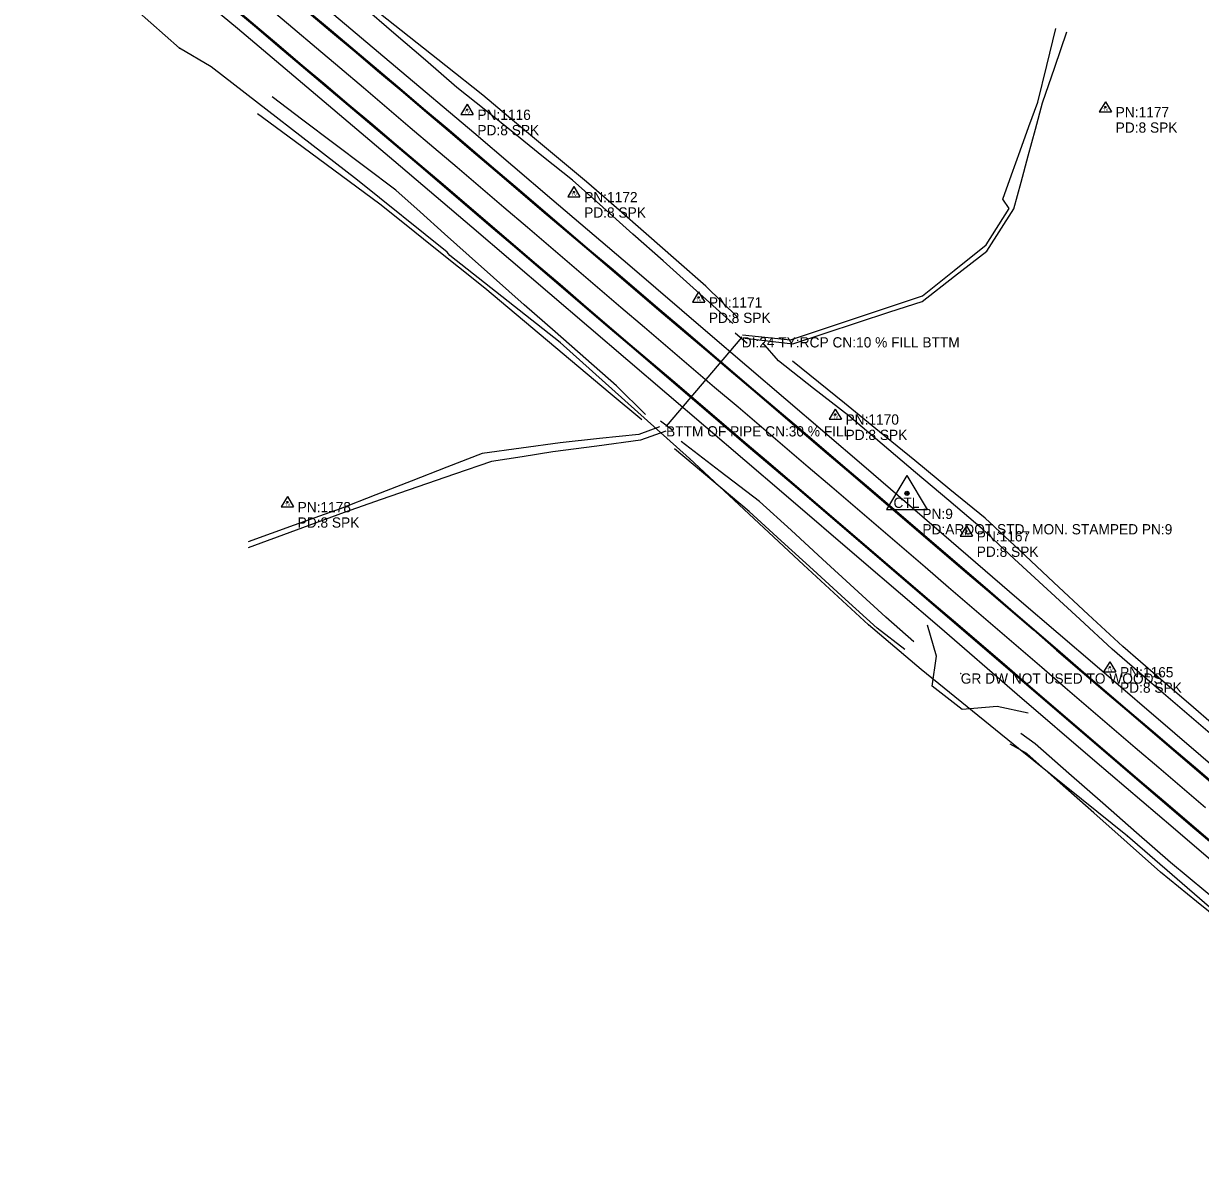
# Model space of a CAD drawing. Extents: x 878399 to 889864, y 1564003 to 1567413.
# Drawn here: x 883520 to 884094, y 1565882 to 1566437 of the extents above; entities that cross this region are included whole.
import ezdxf

# ---------------------------------------------------------------- set-up
doc = ezdxf.new("R2010")
doc.units = 0
for name, color, linetype in [('S_CROSS_DRAIN', 7, 'Continuous'), ('S_CROSS_DRAIN_ANNOT', 7, 'Continuous'), ('S_DITCHLINE', 7, 'Continuous'), ('S_DRG_PT_SYM', 7, 'Continuous'), ('S_DRIVEWAY', 7, 'Continuous'), ('S_EDGE_PAVEMENT', 7, 'Continuous'), ('S_FIBER_OPTIC_CABLE', 7, 'Continuous'), ('S_HEADWALL', 7, 'Continuous'), ('S_MSC_PT_SYM', 7, 'Continuous'), ('S_PAVEMENT_CROWN', 7, 'Continuous'), ('S_PRIMARY_CTL', 7, 'Continuous'), ('S_PRIMARY_CTL_ANNOT', 7, 'Continuous'), ('S_SECONDARY_CTL', 7, 'Continuous'), ('S_SECONDARY_CTL_ANNOT', 7, 'Continuous'), ('S_SHOULDER', 7, 'Continuous'), ('S_SURVEY_TEXT_ANNOT', 7, 'Continuous'), ('S_UTL_PT_SYM', 7, 'Continuous')]:
    doc.layers.add(name, color=color, linetype=linetype)

msp = doc.modelspace()

# ---------------------------------------------------------------- linework, layer by layer
at = {"layer": 'S_CROSS_DRAIN'}
msp.add_line((883870.47, 1566284.25), (883833.58, 1566240.87), dxfattribs=at)
at = {"layer": 'S_DITCHLINE'}
for points in [[(883868.52, 1566293.82), (883852.98, 1566309.2), (883838.44, 1566321.88), (883823.9, 1566334.56), (883809.35, 1566347.24), (883794.81, 1566359.92), (883782.15, 1566370.5), (883769.5, 1566381.09), (883756.84, 1566391.67), (883744.19, 1566402.26), (883726.29, 1566416.45), (883708.4, 1566430.65), (883690.51, 1566444.84), (883672.62, 1566459.03), (883657.19, 1566473.28), (883641.76, 1566487.53), (883626.33, 1566501.78), (883610.9, 1566516.03), (883593.87, 1566529.85), (883576.85, 1566543.67), (883559.83, 1566557.49), (883542.8, 1566571.31), (883526.07, 1566585.55), (883509.35, 1566599.78)], [(883866.04, 1566290.98), (883856.42, 1566299.66), (883846.8, 1566308.34), (883832.09, 1566321.45), (883817.39, 1566334.55), (883802.68, 1566347.66), (883787.98, 1566360.76), (883773.88, 1566372.08), (883759.79, 1566383.39), (883745.69, 1566394.71), (883731.6, 1566406.02), (883716.23, 1566419.25), (883700.87, 1566432.48), (883685.5, 1566445.7)], [(883870.77, 1566285.48), (883894.31, 1566283.02), (883910.36, 1566288.36), (883926.41, 1566293.7), (883942.46, 1566299.04), (883958.51, 1566304.38), (883974.06, 1566316.8), (883989.62, 1566329.22), (884000.82, 1566347.04), (883997.73, 1566351.58), (884001.98, 1566363.38), (884006.24, 1566375.17), (884010.49, 1566386.96), (884014.74, 1566398.75), (884019.13, 1566416.73), (884023.52, 1566434.71)], [(883872.01, 1566283.84), (883895.41, 1566281.01), (883911.16, 1566286.18), (883926.9, 1566291.36), (883942.64, 1566296.54), (883958.39, 1566301.72), (883974.19, 1566314), (883989.99, 1566326.27), (884003.13, 1566346.82), (884006.63, 1566359.75), (884010.13, 1566372.67), (884013.63, 1566385.59), (884017.13, 1566398.51), (884023.06, 1566415.81), (884028.99, 1566433.1)], [(883823.62, 1566246.5), (883809.48, 1566260.51), (883794.47, 1566273.71), (883779.45, 1566286.9), (883764.43, 1566300.1), (883749.42, 1566313.29), (883737.52, 1566323.96), (883725.63, 1566334.63), (883713.73, 1566345.3), (883701.84, 1566355.97), (883686.75, 1566367.33), (883671.65, 1566378.68), (883656.56, 1566390.03), (883641.47, 1566401.38)], [(883821.7, 1566243.92), (883806.37, 1566256.86), (883791.09, 1566269.69), (883775.8, 1566282.53), (883760.51, 1566295.36), (883745.22, 1566308.19), (883732.42, 1566318.41), (883719.62, 1566328.63), (883706.82, 1566338.85), (883694.02, 1566349.07), (883679.1, 1566360.1), (883664.18, 1566371.14), (883649.26, 1566382.17), (883634.35, 1566393.21)], [(884105.66, 1566085.17), (884087.47, 1566100.83), (884069.28, 1566116.48), (884051.09, 1566132.14), (884035.22, 1566146.81), (884019.35, 1566161.47), (884003.47, 1566176.14), (883987.6, 1566190.81), (883971.37, 1566204.59), (883955.13, 1566218.36), (883938.9, 1566232.14), (883922.66, 1566245.92), (883905.51, 1566259.29), (883888.35, 1566272.66), (883880.79, 1566281.54)], [(884107.91, 1566088.85), (884090.66, 1566103.72), (884073.42, 1566118.59), (884056.17, 1566133.46), (884039.4, 1566149.1), (884022.62, 1566164.74), (884005.85, 1566180.39), (883989.08, 1566196.03), (883971.95, 1566210.05), (883954.82, 1566224.08), (883937.69, 1566238.1), (883920.56, 1566252.12), (883907.91, 1566262.38), (883895.27, 1566272.64)], [(883830.39, 1566240.59), (883820.33, 1566236.8), (883801.12, 1566234.81), (883781.9, 1566232.82), (883762.91, 1566230.2), (883743.93, 1566227.58), (883726.64, 1566220.85), (883709.35, 1566214.11), (883692.06, 1566207.38), (883674.77, 1566200.64), (883652.35, 1566192.56), (883629.93, 1566184.47)], [(883833.47, 1566238.51), (883821.12, 1566234.09), (883799.75, 1566231.21), (883778.38, 1566228.32), (883763.41, 1566226), (883748.44, 1566223.67), (883730.51, 1566217.48), (883712.59, 1566211.28), (883694.66, 1566205.09), (883676.73, 1566198.89), (883653.28, 1566190.24), (883629.83, 1566181.6)], [(883949.98, 1566132.05), (883936.43, 1566142.42), (883920.83, 1566156.64), (883905.22, 1566170.85), (883889.62, 1566185.07), (883874.02, 1566199.29), (883855.86, 1566214.58), (883837.71, 1566229.86)], [(883954.37, 1566135.83), (883940.63, 1566147.8), (883925.25, 1566161.91), (883909.87, 1566176.03), (883894.49, 1566190.14), (883879.11, 1566204.25), (883860, 1566218.85), (883840.9, 1566233.44)], [(884240.72, 1565883.62), (884225.82, 1565898.5), (884210.91, 1565913.38), (884194.38, 1565926.67), (884177.84, 1565939.96), (884161.31, 1565953.26), (884144.77, 1565966.55), (884127.24, 1565980.78), (884109.7, 1565995.01), (884092.16, 1566009.24), (884074.62, 1566023.47), (884058.32, 1566037.93), (884042.02, 1566052.39), (884025.72, 1566066.85), (884009.41, 1566081.31), (884001.3, 1566085.82)], [(884242.45, 1565886.54), (884228.13, 1565901.45), (884213.8, 1565916.37), (884197.57, 1565929.98), (884181.35, 1565943.6), (884165.12, 1565957.21), (884148.89, 1565970.82), (884131.52, 1565985.16), (884114.14, 1565999.51), (884096.77, 1566013.85), (884079.4, 1566028.2), (884062.93, 1566042.65), (884046.46, 1566057.1), (884029.99, 1566071.55), (884013.52, 1566086), (884006.53, 1566091.04)]]:
    msp.add_lwpolyline(points, dxfattribs=at)
at = {"layer": 'S_DRG_PT_SYM'}
for points in [[(883870.47, 1566284.25), (883870.47, 1566284.3), (883870.47, 1566284.25), (883870.42, 1566284.25), (883870.47, 1566284.25), (883870.47, 1566284.2), (883870.47, 1566284.25), (883870.52, 1566284.25)], [(883833.58, 1566240.87), (883833.58, 1566240.92), (883833.58, 1566240.87), (883833.53, 1566240.87), (883833.58, 1566240.87), (883833.58, 1566240.82), (883833.58, 1566240.87), (883833.63, 1566240.87)]]:
    msp.add_lwpolyline(points, dxfattribs=at)
at = {"layer": 'S_DRIVEWAY'}
msp.add_lwpolyline([(884010.01, 1566101.03), (883994.98, 1566104.33), (883977.84, 1566102.76), (883963.25, 1566114.16), (883965.33, 1566128.79), (883961.02, 1566143.85)], dxfattribs=at)
at = {"layer": 'S_EDGE_PAVEMENT'}
for points in [[(883621.41, 1566445.63), (883632.92, 1566436.01), (883644.37, 1566426.32), (883655.75, 1566416.68), (883655.75, 1566416.68), (883655.75, 1566416.68), (883667.2, 1566406.99), (883678.66, 1566397.31), (883690.12, 1566387.62), (883701.58, 1566377.94), (883713.01, 1566368.23), (883713.01, 1566368.23), (883724.4, 1566358.54), (883735.82, 1566348.81), (883735.82, 1566348.81), (883735.82, 1566348.81), (883747.23, 1566339.08), (883758.63, 1566329.32), (883770.02, 1566319.56), (883781.42, 1566309.81), (883792.87, 1566300.02), (883804.27, 1566290.27), (883815.67, 1566280.52), (883827.05, 1566270.8), (883838.46, 1566261.06), (883849.87, 1566251.32), (883861.28, 1566241.58), (883861.28, 1566241.58), (883872.69, 1566231.85), (883884.11, 1566222.12), (883895.53, 1566212.39), (883906.92, 1566202.63), (883918.3, 1566192.9), (883929.7, 1566183.14), (883941.09, 1566173.39), (883952.49, 1566163.63), (883963.89, 1566153.88), (883975.28, 1566144.11), (883986.66, 1566134.34), (883998.03, 1566124.58), (884009.42, 1566114.8), (884020.8, 1566105.03), (884032.18, 1566095.26), (884043.56, 1566085.49), (884054.96, 1566075.74), (884066.42, 1566065.96), (884066.42, 1566065.96), (884077.82, 1566056.22), (884089.24, 1566046.48), (884100.65, 1566036.75)], [(883621.89, 1566445.86), (883633.4, 1566436.24), (883644.85, 1566426.55), (883656.23, 1566416.92), (883656.23, 1566416.92), (883656.23, 1566416.92), (883667.68, 1566407.22), (883679.13, 1566397.54), (883690.59, 1566387.86), (883702.05, 1566378.18), (883713.48, 1566368.46), (883713.48, 1566368.46), (883724.87, 1566358.77), (883736.29, 1566349.05), (883736.29, 1566349.05), (883736.29, 1566349.05), (883747.7, 1566339.31), (883759.09, 1566329.56), (883770.49, 1566319.8), (883781.88, 1566310.05), (883793.33, 1566300.26), (883804.73, 1566290.51), (883816.14, 1566280.76), (883827.52, 1566271.04), (883838.92, 1566261.3), (883850.33, 1566251.56), (883861.74, 1566241.83), (883861.74, 1566241.83), (883873.16, 1566232.09), (883884.57, 1566222.36), (883895.99, 1566212.63), (883907.38, 1566202.88), (883918.76, 1566193.14), (883930.15, 1566183.39), (883941.55, 1566173.63), (883952.95, 1566163.88), (883964.34, 1566154.12), (883975.73, 1566144.36), (883987.11, 1566134.59), (883998.49, 1566124.82), (884009.87, 1566115.05), (884021.25, 1566105.28), (884032.63, 1566095.51), (884044.02, 1566085.74), (884055.42, 1566075.99), (884066.87, 1566066.21), (884066.87, 1566066.21), (884078.27, 1566056.47), (884089.69, 1566046.73), (884101.1, 1566037.01)], [(883658.5, 1566443.15), (883670.03, 1566433.45), (883670.03, 1566433.45), (883681.5, 1566423.79), (883681.5, 1566423.79), (883681.5, 1566423.79), (883692.98, 1566414.13), (883692.98, 1566414.13), (883704.44, 1566404.45), (883704.44, 1566404.45), (883715.88, 1566394.75), (883715.88, 1566394.75), (883727.33, 1566385.05), (883738.79, 1566375.32), (883750.2, 1566365.57), (883761.6, 1566355.83), (883761.6, 1566355.83), (883773.01, 1566346.08), (883773.01, 1566346.08), (883784.43, 1566336.36), (883795.86, 1566326.64), (883807.25, 1566316.95), (883818.67, 1566307.23), (883818.67, 1566307.23), (883818.67, 1566307.23), (883830.09, 1566297.5), (883841.53, 1566287.75), (883852.95, 1566278.03), (883864.37, 1566268.3), (883875.79, 1566258.57), (883887.21, 1566248.84), (883898.62, 1566239.11), (883910.04, 1566229.38), (883921.46, 1566219.65), (883932.88, 1566209.9), (883944.29, 1566200.16), (883955.7, 1566190.42), (883955.7, 1566190.42), (883955.7, 1566190.42), (883967.1, 1566180.67), (883978.48, 1566170.9), (883989.87, 1566161.13), (884001.25, 1566151.35), (884012.61, 1566141.55), (884023.97, 1566131.75), (884035.32, 1566121.95), (884035.32, 1566121.95), (884046.71, 1566112.19), (884058.12, 1566102.44), (884069.52, 1566092.7), (884080.89, 1566082.99), (884092.29, 1566073.24), (884103.7, 1566063.5)], [(883658.98, 1566443.38), (883670.5, 1566433.68), (883670.5, 1566433.68), (883681.98, 1566424.02), (883681.98, 1566424.02), (883681.98, 1566424.02), (883693.45, 1566414.36), (883693.45, 1566414.36), (883704.91, 1566404.68), (883704.91, 1566404.68), (883716.35, 1566394.98), (883716.35, 1566394.98), (883727.8, 1566385.29), (883739.26, 1566375.55), (883750.66, 1566365.81), (883762.07, 1566356.06), (883762.07, 1566356.06), (883773.47, 1566346.32), (883773.47, 1566346.32), (883784.9, 1566336.6), (883796.32, 1566326.88), (883807.71, 1566317.19), (883819.13, 1566307.47), (883819.13, 1566307.47), (883819.13, 1566307.47), (883830.55, 1566297.74), (883841.99, 1566287.99), (883853.41, 1566278.27), (883864.83, 1566268.54), (883876.25, 1566258.81), (883887.67, 1566249.08), (883899.08, 1566239.36), (883910.5, 1566229.63), (883921.92, 1566219.9), (883933.34, 1566210.14), (883944.75, 1566200.4), (883956.16, 1566190.66), (883956.16, 1566190.66), (883956.16, 1566190.66), (883967.56, 1566180.91), (883978.94, 1566171.14), (883990.32, 1566161.37), (884001.7, 1566151.6), (884013.06, 1566141.8), (884024.42, 1566132), (884035.78, 1566122.2), (884035.78, 1566122.2), (884047.17, 1566112.44), (884058.57, 1566102.69), (884069.97, 1566092.95), (884081.34, 1566083.24), (884092.75, 1566073.49), (884104.15, 1566063.75)]]:
    msp.add_lwpolyline(points, dxfattribs=at)
at = {"layer": 'S_FIBER_OPTIC_CABLE'}
for p, q in [((883596.33, 1566425.08), (883556.64, 1566460.44)), ((883611.79, 1566416.06), (883596.33, 1566425.08)), ((883683.18, 1566360.86), (883611.79, 1566416.06)), ((883726.78, 1566325.69), (883683.18, 1566360.86)), ((883728.15, 1566324.09), (883726.78, 1566325.69)), ((883781.99, 1566281.71), (883728.15, 1566324.09)), ((883844.93, 1566225.21), (883781.99, 1566281.71)), ((883900.64, 1566173.32), (883844.93, 1566225.21)), ((883932.2, 1566144.11), (883900.64, 1566173.32)), ((883957.95, 1566122.32), (883932.2, 1566144.11)), ((884005.31, 1566083.73), (883957.95, 1566122.32)), ((884058.45, 1566040.97), (884005.31, 1566083.73)), ((884110.46, 1565996.06), (884058.45, 1566040.97))]:
    msp.add_line(p, q, dxfattribs=at)
at = {"layer": 'S_HEADWALL'}
for points in [[(883867.28, 1566286.41), (883873.14, 1566281.37)], [(883836.94, 1566238.74), (883830.91, 1566243.31)]]:
    msp.add_lwpolyline(points, dxfattribs=at)
at = {"layer": 'S_MSC_PT_SYM'}
msp.add_lwpolyline([(883977.22, 1566120.39), (883977.22, 1566120.44), (883977.22, 1566120.39), (883977.17, 1566120.39), (883977.22, 1566120.39), (883977.22, 1566120.34), (883977.22, 1566120.39), (883977.27, 1566120.39)], dxfattribs=at)
at = {"layer": 'S_PAVEMENT_CROWN'}
msp.add_lwpolyline([(883640.18, 1566444.66), (883651.67, 1566435.01), (883663.12, 1566425.34), (883674.57, 1566415.64), (883686.02, 1566405.95), (883697.46, 1566396.24), (883697.46, 1566396.24), (883708.87, 1566386.51), (883708.87, 1566386.51), (883720.29, 1566376.78), (883731.71, 1566367.06), (883731.71, 1566367.06), (883743.12, 1566357.32), (883743.12, 1566357.32), (883754.53, 1566347.59), (883754.53, 1566347.59), (883765.95, 1566337.85), (883765.95, 1566337.85), (883777.36, 1566328.11), (883788.77, 1566318.37), (883788.77, 1566318.37), (883800.18, 1566308.63), (883800.18, 1566308.63), (883800.18, 1566308.63), (883811.59, 1566298.89), (883823.01, 1566289.16), (883834.42, 1566279.44), (883845.84, 1566269.71), (883857.26, 1566259.98), (883868.68, 1566250.26), (883880.11, 1566240.53), (883891.52, 1566230.79), (883902.92, 1566221.05), (883914.33, 1566211.3), (883925.73, 1566201.56), (883925.73, 1566201.56), (883925.73, 1566201.56), (883937.12, 1566191.79), (883948.5, 1566182.02), (883959.89, 1566172.26), (883959.89, 1566172.26), (883971.26, 1566162.48), (883982.64, 1566152.7), (883994.01, 1566142.92), (883994.01, 1566142.92), (884005.39, 1566133.14), (884016.76, 1566123.36), (884028.14, 1566113.58), (884028.14, 1566113.58), (884039.52, 1566103.8), (884050.91, 1566094.05), (884062.31, 1566084.3), (884073.71, 1566074.54), (884085.12, 1566064.8), (884096.53, 1566055.06)], dxfattribs=at)
at = {"layer": 'S_PRIMARY_CTL'}
for p, q in [((883951.02, 1566216.84), (883940.98, 1566200.32)), ((883951.02, 1566216.84), (883960.84, 1566200.32)), ((883940.98, 1566200.32), (883960.84, 1566200.32))]:
    msp.add_line(p, q, dxfattribs=at)
for radius in [1.04, 0.609, 0.344]:
    msp.add_circle((883951.02, 1566208.14), radius, dxfattribs=at)
at = {"layer": 'S_SECONDARY_CTL'}
for p, q in [((883736.6, 1566397.78), (883733.59, 1566392.83)), ((883736.6, 1566397.78), (883739.54, 1566392.83)), ((884047.76, 1566399.05), (884044.75, 1566394.1)), ((884047.76, 1566399.05), (884050.7, 1566394.1)), ((883733.59, 1566392.83), (883739.54, 1566392.83)), ((884044.75, 1566394.1), (884050.7, 1566394.1)), ((883788.65, 1566357.64), (883785.64, 1566352.68)), ((883788.65, 1566357.64), (883791.6, 1566352.68)), ((883785.64, 1566352.68), (883791.6, 1566352.68)), ((883849.44, 1566306.31), (883846.43, 1566301.35)), ((883849.44, 1566306.31), (883852.39, 1566301.35)), ((883846.43, 1566301.35), (883852.39, 1566301.35)), ((883916.07, 1566249.25), (883913.06, 1566244.29)), ((883916.07, 1566249.25), (883919.02, 1566244.29)), ((883913.06, 1566244.29), (883919.02, 1566244.29)), ((883648.96, 1566206.53), (883645.95, 1566201.58)), ((883648.96, 1566206.53), (883651.91, 1566201.58)), ((883645.95, 1566201.58), (883651.91, 1566201.58)), ((883980.02, 1566192.3), (883977.01, 1566187.35)), ((883980.02, 1566192.3), (883982.97, 1566187.35)), ((883977.01, 1566187.35), (883982.97, 1566187.35)), ((884049.88, 1566126.06), (884046.87, 1566121.11)), ((884049.88, 1566126.06), (884052.83, 1566121.11)), ((884046.87, 1566121.11), (884052.83, 1566121.11))]:
    msp.add_line(p, q, dxfattribs=at)
for centre, radius in [((883736.6, 1566395.17), 0.311), ((883736.6, 1566395.17), 0.183), ((883736.6, 1566395.17), 0.103), ((884047.76, 1566396.44), 0.311), ((884047.76, 1566396.44), 0.183), ((884047.76, 1566396.44), 0.103), ((883788.65, 1566355.03), 0.311), ((883788.65, 1566355.03), 0.183), ((883788.65, 1566355.03), 0.103), ((883849.44, 1566303.7), 0.311), ((883849.44, 1566303.7), 0.183), ((883849.44, 1566303.7), 0.103), ((883916.07, 1566246.64), 0.311), ((883916.07, 1566246.64), 0.183), ((883916.07, 1566246.64), 0.103), ((883648.96, 1566203.92), 0.311), ((883648.96, 1566203.92), 0.183), ((883648.96, 1566203.92), 0.103), ((883980.02, 1566189.69), 0.311), ((883980.02, 1566189.69), 0.183), ((883980.02, 1566189.69), 0.103), ((884049.88, 1566123.45), 0.311), ((884049.88, 1566123.45), 0.183), ((884049.88, 1566123.45), 0.103)]:
    msp.add_circle(centre, radius, dxfattribs=at)
at = {"layer": 'S_SHOULDER'}
for points in [[(883508.31, 1566575.84), (883547.66, 1566544.44), (883586.44, 1566512.88), (883625.11, 1566480.84), (883663.31, 1566448.58), (883701.62, 1566416.27), (883739.86, 1566383.96), (883777.89, 1566351.48), (883815.94, 1566319.17), (883853.96, 1566286.62), (883891.95, 1566254.11), (883929.94, 1566221.59), (883967.85, 1566188.94), (884005.75, 1566156.31), (884043.67, 1566123.7), (884081.66, 1566091.2), (884119.53, 1566058.67), (884157.51, 1566026.01), (884195.58, 1565993.6), (884233.66, 1565961.2), (884271.59, 1565928.53), (884288.54, 1565909.45), (884315.55, 1565882.9), (884321.54, 1565877.6)], [(883509.1, 1566529.69), (883547.7, 1566498.51), (883586.27, 1566466.69), (883624.58, 1566434.92), (883662.64, 1566402.69), (883700.84, 1566370.42), (883738.86, 1566338.05), (883776.89, 1566305.59), (883814.92, 1566272.98), (883852.88, 1566240.51), (883890.94, 1566208.08), (883928.89, 1566175.58), (883966.88, 1566143.07), (884004.67, 1566110.33), (884042.61, 1566077.76), (884080.7, 1566045.23), (884118.58, 1566012.73), (884156.35, 1565979.97), (884194.27, 1565947.36), (884231.98, 1565914.52), (884270.03, 1565882.19), (884310.06, 1565851.92)]]:
    msp.add_lwpolyline(points, dxfattribs=at)
at = {"layer": 'S_UTL_PT_SYM'}
for points in [[(883596.33, 1566425.08), (883596.33, 1566425.13), (883596.33, 1566425.08), (883596.28, 1566425.08), (883596.33, 1566425.08), (883596.33, 1566425.03), (883596.33, 1566425.08), (883596.38, 1566425.08)], [(883611.79, 1566416.06), (883611.79, 1566416.11), (883611.79, 1566416.06), (883611.74, 1566416.06), (883611.79, 1566416.06), (883611.79, 1566416.01), (883611.79, 1566416.06), (883611.84, 1566416.06)], [(883683.18, 1566360.86), (883683.18, 1566360.91), (883683.18, 1566360.86), (883683.13, 1566360.86), (883683.18, 1566360.86), (883683.18, 1566360.81), (883683.18, 1566360.86), (883683.23, 1566360.86)], [(883726.78, 1566325.69), (883726.78, 1566325.74), (883726.78, 1566325.69), (883726.73, 1566325.69), (883726.78, 1566325.69), (883726.78, 1566325.64), (883726.78, 1566325.69), (883726.83, 1566325.69)], [(883728.15, 1566324.09), (883728.15, 1566324.14), (883728.15, 1566324.09), (883728.1, 1566324.09), (883728.15, 1566324.09), (883728.15, 1566324.04), (883728.15, 1566324.09), (883728.2, 1566324.09)], [(883781.99, 1566281.71), (883781.99, 1566281.76), (883781.99, 1566281.71), (883781.94, 1566281.71), (883781.99, 1566281.71), (883781.99, 1566281.66), (883781.99, 1566281.71), (883782.04, 1566281.71)], [(883844.93, 1566225.21), (883844.93, 1566225.26), (883844.93, 1566225.21), (883844.88, 1566225.21), (883844.93, 1566225.21), (883844.93, 1566225.16), (883844.93, 1566225.21), (883844.98, 1566225.21)], [(883900.64, 1566173.32), (883900.64, 1566173.37), (883900.64, 1566173.32), (883900.59, 1566173.32), (883900.64, 1566173.32), (883900.64, 1566173.27), (883900.64, 1566173.32), (883900.69, 1566173.32)], [(883932.2, 1566144.11), (883932.2, 1566144.16), (883932.2, 1566144.11), (883932.15, 1566144.11), (883932.2, 1566144.11), (883932.2, 1566144.06), (883932.2, 1566144.11), (883932.25, 1566144.11)], [(883957.95, 1566122.32), (883957.95, 1566122.37), (883957.95, 1566122.32), (883957.9, 1566122.32), (883957.95, 1566122.32), (883957.95, 1566122.27), (883957.95, 1566122.32), (883958, 1566122.32)], [(884005.31, 1566083.73), (884005.31, 1566083.78), (884005.31, 1566083.73), (884005.26, 1566083.73), (884005.31, 1566083.73), (884005.31, 1566083.68), (884005.31, 1566083.73), (884005.36, 1566083.73)], [(884058.45, 1566040.97), (884058.45, 1566041.02), (884058.45, 1566040.97), (884058.4, 1566040.97), (884058.45, 1566040.97), (884058.45, 1566040.92), (884058.45, 1566040.97), (884058.5, 1566040.97)]]:
    msp.add_lwpolyline(points, dxfattribs=at)

# ---------------------------------------------------------------- texts
at = {"layer": 'S_CROSS_DRAIN_ANNOT'}
for s, p in [('DI:24 TY:RCP CN:10 % FILL BTTM ', (883870.47, 1566279.25)), ('BTTM OF PIPE CN:30 % FILL', (883833.58, 1566235.87))]:
    msp.add_text(s, height=5, dxfattribs=at).set_placement(p)
at = {"layer": 'S_PRIMARY_CTL'}
msp.add_text('CTL', height=5, rotation=360, dxfattribs=at).set_placement((883944.43, 1566201.06))
at = {"layer": 'S_PRIMARY_CTL_ANNOT'}
for s, p in [('PN:9', (883958.52, 1566195.64)), ('PD:ARDOT STD. MON. STAMPED PN:9', (883958.52, 1566188.14))]:
    msp.add_text(s, height=5, dxfattribs=at).set_placement(p)
at = {"layer": 'S_SECONDARY_CTL'}
for p in [(884046.55, 1566394.43), (883735.39, 1566393.16), (883787.45, 1566353.01), (883848.24, 1566301.69), (883914.87, 1566244.62), (883647.76, 1566201.91), (883978.82, 1566187.68), (884048.67, 1566121.44)]:
    msp.add_text('TV', height=1.5, rotation=360, dxfattribs=at).set_placement(p)
at = {"layer": 'S_SECONDARY_CTL_ANNOT'}
for s, p in [('PN:1116', (883741.6, 1566390.17)), ('PN:1177', (884052.76, 1566391.44)), ('PD:8 SPK', (883741.6, 1566382.67)), ('PD:8 SPK', (884052.76, 1566383.94)), ('PN:1172', (883793.65, 1566350.03)), ('PD:8 SPK', (883793.65, 1566342.53)), ('PN:1171', (883854.44, 1566298.7)), ('PD:8 SPK', (883854.44, 1566291.2)), ('PN:1170', (883921.07, 1566241.64)), ('PD:8 SPK', (883921.07, 1566234.14)), ('PN:1178', (883653.96, 1566198.92)), ('PD:8 SPK', (883653.96, 1566191.42)), ('PN:1167', (883985.02, 1566184.69)), ('PD:8 SPK', (883985.02, 1566177.19)), ('PN:1165', (884054.88, 1566118.45)), ('PD:8 SPK', (884054.88, 1566110.95))]:
    msp.add_text(s, height=5, dxfattribs=at).set_placement(p)
at = {"layer": 'S_SURVEY_TEXT_ANNOT'}
msp.add_text('GR DW NOT USED TO WOODS', height=5, dxfattribs=at).set_placement((883977.22, 1566115.39))

doc.saveas('drawing.dxf')
